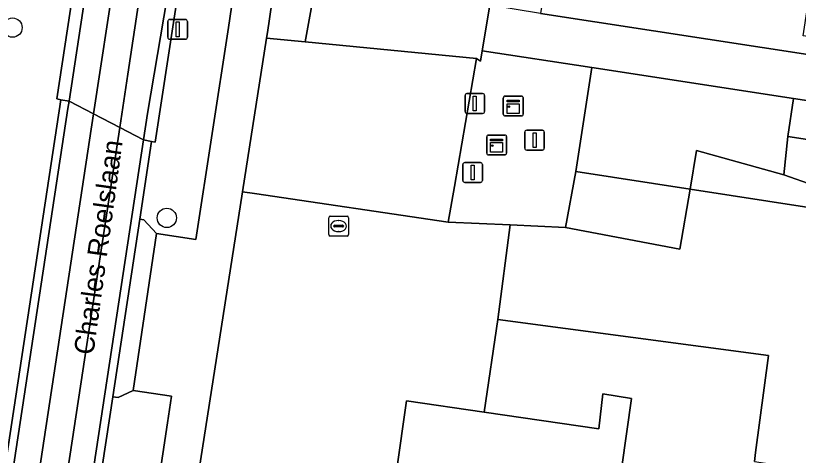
# Model space of a CAD drawing. Extents: x 161090 to 161692, y 379509 to 380907.
# Drawn here: x 161342.3 to 161381.89, y 380360.48 to 380382.7 of the extents above; entities that cross this region are included whole.
import ezdxf

# ---------------------------------------------------------------- set-up
doc = ezdxf.new("R2010")
doc.units = 0
for name, color, linetype in [('IMGEO_Berm_open', 7, 'Continuous'), ('IMGEO_Boom', 7, 'Continuous'), ('IMGEO_Groenvoorziening', 7, 'Continuous'), ('IMGEO_Hek', 7, 'Continuous'), ('IMGEO_Kast', 7, 'Continuous'), ('IMGEO_Kolk', 7, 'Continuous'), ('IMGEO_Lichtmast', 7, 'Continuous'), ('IMGEO_Openbare_ruimte_label', 7, 'Continuous'), ('IMGEO_Pand', 7, 'Continuous'), ('IMGEO_Rijbaan_lokaal_gesloten', 7, 'Continuous'), ('IMGEO_Rijbaan_lokaal_open', 7, 'Continuous'), ('IMGEO_Voetpad_gesloten', 7, 'Continuous'), ('IMGEO_Voetpad_open', 7, 'Continuous')]:
    doc.layers.add(name, color=color, linetype=linetype)

msp = doc.modelspace()

# ---------------------------------------------------------------- linework, layer by layer
at = {"layer": 'IMGEO_Berm_open'}
for points in [[(161355.725, 380448.967), (161357.571, 380461.128), (161356.996, 380461.235), (161355.421, 380450.894), (161355.14, 380449.051), (161354.011, 380441.643), (161344.389, 380378.487), (161344.59, 380378.452), (161345.007, 380378.379)], [(161359.36, 380442.076), (161359.664, 380444.186), (161360.3, 380448.307), (161362.175, 380460.46), (161361.586, 380460.548), (161359.751, 380448.386), (161350.135, 380384.631), (161348.977, 380377.751), (161348.775, 380376.428), (161349.181, 380376.34), (161349.368, 380376.3), (161352.303, 380395.563), (161352.6, 380397.59)], [(161344.951, 380378.008), (161345.007, 380378.379), (161344.59, 380378.452), (161324.892, 380248.973), (161324.162, 380244.173), (161321.656, 380227.7), (161322.076, 380227.626)], [(161334.619, 380280.903), (161334.854, 380282.447), (161335.341, 380285.645), (161335.901, 380289.318), (161337.021, 380296.658), (161337.547, 380300.102), (161339.301, 380311.601), (161339.84, 380315.127), (161341.641, 380326.929), (161347.212, 380363.435), (161348.583, 380372.419), (161349.181, 380376.34), (161348.775, 380376.428), (161335.506, 380289.381), (161325.446, 380223.42), (161325.852, 380223.354), (161325.866, 380223.448)]]:
    msp.add_lwpolyline(points, close=True, dxfattribs=at)
at = {"layer": 'IMGEO_Boom'}
for centre in [(161342.145, 380382.093), (161349.949, 380372.477)]:
    msp.add_circle(centre, 0.489, dxfattribs=at)
at = {"layer": 'IMGEO_Groenvoorziening'}
for points in [[(161348.425, 380442.457), (161348.083, 380442.507), (161347.809, 380440.721), (161343.094, 380410), (161341.258, 380398.041), (161340.185, 380394.742), (161339.9, 380392.897), (161338.488, 380392.532), (161338.415, 380392.044), (161337.94, 380388.87), (161317.884, 380254.93), (161315.312, 380255.309), (161314.369, 380249.618), (161321.492, 380248.501), (161324.892, 380248.973), (161344.59, 380378.452), (161344.389, 380378.487), (161354.011, 380441.643), (161348.796, 380442.403), (161319.973, 380254.612), (161319.602, 380254.669)], [(161359.874, 380397.513), (161357.564, 380396.909), (161356.103, 380388.816), (161355.909, 380387.739), (161355.043, 380381.85), (161354.998, 380381.564), (161356.953, 380381.374)], [(161353.938, 380388.06), (161354.108, 380389.079), (161354.875, 380393.67), (161355.424, 380396.33), (161352.303, 380395.563), (161349.368, 380376.3), (161349.181, 380376.34), (161348.583, 380372.419), (161348.788, 380372.383), (161349.424, 380371.695), (161351.411, 380371.391), (161353.061, 380382.104)], [(161384.783, 380376.062), (161381.353, 380376.586), (161381.163, 380374.657), (161382.693, 380374.109), (161384.386, 380373.456), (161384.274, 380372.724), (161463.887, 380360.513), (161466.132, 380360.169), (161466.151, 380360.297), (161470.678, 380359.631), (161470.78, 380360.312), (161470.639, 380361.064), (161470.9, 380361.114), (161471.145, 380362.753), (161471.162, 380362.866)], [(161349.991, 380362.127), (161350.192, 380363.472), (161348.24, 380363.761), (161347.497, 380363.399), (161347.212, 380363.435), (161341.641, 380326.929), (161344.627, 380326.528)]]:
    msp.add_lwpolyline(points, close=True, dxfattribs=at)
msp.add_lwpolyline([(161364.934, 380398.835), (161359.874, 380397.513), (161356.953, 380381.374), (161365.618, 380380.527), (161365.81, 380380.399), (161365.899, 380380.919), (161366.293, 380383.221), (161368.167, 380395.546), (161366.26, 380395.866), (161366.584, 380397.823)], dxfattribs=at)
at = {"layer": 'IMGEO_Hek'}
for points in [[(161365.618, 380380.527), (161364.502, 380374.068)], [(161370.631, 380374.817), (161371.438, 380380.074)], [(161370.107, 380371.989), (161370.631, 380374.817)], [(161384.274, 380372.724), (161370.631, 380374.817)], [(161364.502, 380374.068), (161364.182, 380372.262)], [(161364.182, 380372.262), (161354.392, 380373.71)], [(161364.182, 380372.262), (161367.309, 380372.118)], [(161367.309, 380372.118), (161366.698, 380367.337)], [(161367.309, 380372.118), (161370.107, 380371.989)], [(161366.002, 380362.661), (161366.698, 380367.337)], [(161366.698, 380367.337), (161380.378, 380365.515), (161379.726, 380360.615), (161379.666, 380360.168)]]:
    msp.add_lwpolyline(points, dxfattribs=at)
at = {"layer": 'IMGEO_Kast'}
for p, q in [((161366.969, 380377.708), (161366.969, 380378.549)), ((161366.969, 380378.549), (161366.969, 380377.708)), ((161367.044, 380378.633), (161367.885, 380378.633)), ((161367.885, 380378.633), (161367.044, 380378.633)), ((161367.969, 380378.558), (161367.969, 380377.717)), ((161367.969, 380377.717), (161367.969, 380378.558)), ((161367.894, 380377.633), (161367.053, 380377.633)), ((161367.053, 380377.633), (161367.894, 380377.633)), ((161366.133, 380375.741), (161366.133, 380376.582)), ((161366.133, 380376.582), (161366.133, 380375.741)), ((161366.208, 380376.666), (161367.049, 380376.666)), ((161367.049, 380376.666), (161366.208, 380376.666)), ((161367.133, 380376.591), (161367.133, 380375.75)), ((161367.133, 380375.75), (161367.133, 380376.591)), ((161367.058, 380375.666), (161366.217, 380375.666)), ((161366.217, 380375.666), (161367.058, 380375.666))]:
    msp.add_line(p, q, dxfattribs=at)
for points in [[(161367.164, 380378.423), (161367.764, 380378.423), (161367.764, 380378.338), (161367.164, 380378.338), (161367.164, 380378.423)], [(161367.164, 380378.248), (161367.764, 380378.248), (161367.764, 380377.759), (161367.164, 380377.759), (161367.164, 380378.248)], [(161366.328, 380376.456), (161366.928, 380376.456), (161366.928, 380376.371), (161366.328, 380376.371), (161366.328, 380376.456)], [(161366.328, 380376.281), (161366.928, 380376.281), (161366.928, 380375.792), (161366.328, 380375.792), (161366.328, 380376.281)]]:
    msp.add_lwpolyline(points, dxfattribs=at)
for centre in [(161367.248, 380378.097), (161366.412, 380376.13)]:
    msp.add_circle(centre, 0.0377, dxfattribs=at)
for centre, start, end in [((161367.047, 380378.555), 92.4484, 184.2845), ((161367.047, 380378.555), 92.4484, 184.2845), ((161367.891, 380378.555), 2.4484, 94.2845), ((161367.891, 380378.555), 2.4484, 94.2845), ((161367.047, 380377.711), 182.4484, 274.2845), ((161367.047, 380377.711), 182.4484, 274.2845), ((161367.891, 380377.711), 272.4484, 4.2845), ((161367.891, 380377.711), 272.4484, 4.2845), ((161366.211, 380376.588), 92.4484, 184.2845), ((161366.211, 380376.588), 92.4484, 184.2845), ((161367.055, 380376.588), 2.4484, 94.2845), ((161367.055, 380376.588), 2.4484, 94.2845), ((161366.211, 380375.744), 182.4484, 274.2845), ((161366.211, 380375.744), 182.4484, 274.2845), ((161367.055, 380375.744), 272.4484, 4.2845), ((161367.055, 380375.744), 272.4484, 4.2845)]:
    msp.add_arc(centre, 0.0779, start, end, dxfattribs=at)
at = {"layer": 'IMGEO_Kolk'}
for p, q in [((161358.139, 380371.636), (161358.139, 380372.488)), ((161358.214, 380372.562), (161359.066, 380372.562)), ((161359.14, 380372.488), (161359.14, 380371.636)), ((161358.441, 380372.105), (161358.839, 380372.105)), ((161358.627, 380372.342), (161358.652, 380372.342)), ((161358.398, 380372.056), (161358.398, 380372.068)), ((161358.836, 380372.019), (161358.438, 380372.019)), ((161358.65, 380371.782), (161358.625, 380371.782)), ((161358.882, 380372.068), (161358.882, 380372.056)), ((161359.066, 380371.562), (161358.214, 380371.562))]:
    msp.add_line(p, q, dxfattribs=at)
for points in [[(161358.139, 380371.636), (161358.139, 380372.488)], [(161358.214, 380372.562), (161359.066, 380372.562)], [(161359.14, 380372.488), (161359.14, 380371.636)], [(161359.066, 380371.562), (161358.214, 380371.562)]]:
    msp.add_lwpolyline(points, dxfattribs=at)
for centre, radius, start, end in [((161358.216, 380372.486), 0.0765, 91.552, 178.448), ((161358.216, 380372.486), 0.0765, 91.552, 178.448), ((161359.064, 380372.486), 0.0765, 1.552, 88.448), ((161359.064, 380372.486), 0.0765, 1.552, 88.448), ((161358.438, 380372.065), 0.0403, 85.8775, 175.7526), ((161358.843, 380372.067), 0.0386, 1.7309, 96.639), ((161358.435, 380372.055), 0.0366, 178.938, 274.7102), ((161358.839, 380372.062), 0.043, 264.8664, 352.4533), ((161358.216, 380371.638), 0.0765, 181.552, 268.448), ((161358.216, 380371.638), 0.0765, 181.552, 268.448), ((161359.064, 380371.638), 0.0765, 271.552, 358.448), ((161359.064, 380371.638), 0.0765, 271.552, 358.448)]:
    msp.add_arc(centre, radius, start, end, dxfattribs=at)
for centre, major_axis, ratio, start_param, end_param in [((161358.626, 380372.062), (-0.387, 0.002), 0.722429, 4.712389, 7.853982), ((161358.651, 380372.062), (-0.39, 0.002), 0.717154, 1.570796, 4.712389)]:
    msp.add_ellipse(centre, major_axis=major_axis, ratio=ratio, start_param=start_param, end_param=end_param, dxfattribs=at)
at = {"layer": 'IMGEO_Lichtmast'}
for p, q in [((161349.998, 380381.605), (161349.998, 380382.405)), ((161349.998, 380382.405), (161349.998, 380381.605)), ((161350.098, 380382.505), (161350.888, 380382.505)), ((161350.888, 380382.505), (161350.098, 380382.505)), ((161350.988, 380382.405), (161350.988, 380381.605)), ((161350.988, 380381.605), (161350.988, 380382.405)), ((161350.888, 380381.505), (161350.098, 380381.505)), ((161350.098, 380381.505), (161350.888, 380381.505)), ((161365.031, 380377.861), (161365.031, 380378.661)), ((161365.031, 380378.661), (161365.031, 380377.861)), ((161365.131, 380378.761), (161365.921, 380378.761)), ((161365.921, 380378.761), (161365.131, 380378.761)), ((161366.021, 380378.661), (161366.021, 380377.861)), ((161366.021, 380377.861), (161366.021, 380378.661)), ((161365.921, 380377.761), (161365.131, 380377.761)), ((161365.131, 380377.761), (161365.921, 380377.761)), ((161368.152, 380376.906), (161368.942, 380376.906)), ((161368.942, 380376.906), (161368.152, 380376.906)), ((161368.052, 380376.006), (161368.052, 380376.806)), ((161368.052, 380376.806), (161368.052, 380376.006)), ((161369.042, 380376.806), (161369.042, 380376.006)), ((161369.042, 380376.006), (161369.042, 380376.806)), ((161368.942, 380375.906), (161368.152, 380375.906)), ((161368.152, 380375.906), (161368.942, 380375.906)), ((161365.02, 380375.269), (161365.81, 380375.269)), ((161365.81, 380375.269), (161365.02, 380375.269)), ((161364.92, 380374.369), (161364.92, 380375.169)), ((161364.92, 380375.169), (161364.92, 380374.369)), ((161365.91, 380375.169), (161365.91, 380374.369)), ((161365.91, 380374.369), (161365.91, 380375.169)), ((161365.81, 380374.269), (161365.02, 380374.269)), ((161365.02, 380374.269), (161365.81, 380374.269))]:
    msp.add_line(p, q, dxfattribs=at)
for points in [[(161350.418, 380382.38), (161350.568, 380382.38), (161350.568, 380381.63), (161350.418, 380381.63), (161350.418, 380382.38)], [(161365.451, 380378.636), (161365.601, 380378.636), (161365.601, 380377.886), (161365.451, 380377.886), (161365.451, 380378.636)], [(161368.472, 380376.781), (161368.622, 380376.781), (161368.622, 380376.031), (161368.472, 380376.031), (161368.472, 380376.781)], [(161365.34, 380375.144), (161365.49, 380375.144), (161365.49, 380374.394), (161365.34, 380374.394), (161365.34, 380375.144)]]:
    msp.add_lwpolyline(points, dxfattribs=at)
for centre, start, end in [((161350.098, 380382.405), 90, 180), ((161350.098, 380382.405), 90, 180), ((161350.888, 380382.405), 0, 90), ((161350.888, 380382.405), 360, 90), ((161350.098, 380381.605), 180, 270), ((161350.098, 380381.605), 180, 270), ((161350.888, 380381.605), 270, 0), ((161350.888, 380381.605), 270, 0), ((161365.131, 380378.661), 90, 180), ((161365.131, 380378.661), 90, 180), ((161365.921, 380378.661), 0, 90), ((161365.921, 380378.661), 360, 90), ((161365.131, 380377.861), 180, 270), ((161365.131, 380377.861), 180, 270), ((161365.921, 380377.861), 270, 0), ((161365.921, 380377.861), 270, 0), ((161368.152, 380376.806), 90, 180), ((161368.152, 380376.806), 90, 180), ((161368.942, 380376.806), 0, 90), ((161368.942, 380376.806), 360, 90), ((161368.152, 380376.006), 180, 270), ((161368.152, 380376.006), 180, 270), ((161368.942, 380376.006), 270, 0), ((161368.942, 380376.006), 270, 0), ((161365.02, 380375.169), 90, 180), ((161365.02, 380375.169), 90, 180), ((161365.81, 380375.169), 0, 90), ((161365.81, 380375.169), 360, 90), ((161365.02, 380374.369), 180, 270), ((161365.02, 380374.369), 180, 270), ((161365.81, 380374.369), 270, 0), ((161365.81, 380374.369), 270, 0)]:
    msp.add_arc(centre, 0.1, start, end, dxfattribs=at)
at = {"layer": 'IMGEO_Pand'}
msp.add_lwpolyline([(161372.961, 380359.891), (161373.459, 380363.357), (161372.008, 380363.588), (161371.8, 380361.818), (161366.002, 380362.661), (161362.072, 380363.233), (161361.053, 380356.126)], dxfattribs=at)
at = {"layer": 'IMGEO_Rijbaan_lokaal_gesloten'}
for points in [[(161359.092, 380463.074), (161357.904, 380463.25), (161357.736, 380462.181), (161357.571, 380461.128), (161355.725, 380448.967), (161345.007, 380378.379), (161346.249, 380377.736), (161347.339, 380384.899), (161352.727, 380420.46), (161357.973, 380455.328)], [(161348.977, 380377.751), (161350.135, 380384.631), (161359.751, 380448.386), (161361.586, 380460.548), (161361.602, 380460.656), (161361.863, 380462.665), (161360.548, 380462.859), (161354.389, 380422.138), (161347.982, 380379.737), (161347.572, 380377.051), (161348.775, 380376.428)]]:
    msp.add_lwpolyline(points, close=True, dxfattribs=at)
for points in [[(161317.471, 380188.836), (161329.956, 380271.064), (161337.144, 380317.912), (161346.249, 380377.736), (161345.007, 380378.379), (161344.951, 380378.008), (161322.076, 380227.626)], [(161325.446, 380223.42), (161335.506, 380289.381), (161348.775, 380376.428), (161347.572, 380377.051), (161337.64, 380311.897), (161331.61, 380272.482), (161327.257, 380243.533)]]:
    msp.add_lwpolyline(points, dxfattribs=at)
at = {"layer": 'IMGEO_Rijbaan_lokaal_open'}
for points in [[(161360.548, 380462.859), (161361.17, 380466.972), (161359.681, 380467.147), (161359.092, 380463.074), (161357.973, 380455.328), (161352.727, 380420.46), (161347.339, 380384.899), (161346.249, 380377.736), (161347.572, 380377.051), (161347.982, 380379.737), (161354.389, 380422.138)], [(161347.572, 380377.051), (161346.249, 380377.736), (161337.144, 380317.912), (161329.956, 380271.064), (161317.471, 380188.836), (161318.978, 380188.612), (161322.079, 380209.661), (161327.257, 380243.533), (161331.61, 380272.482), (161337.64, 380311.897)]]:
    msp.add_lwpolyline(points, close=True, dxfattribs=at)
at = {"layer": 'IMGEO_Voetpad_gesloten'}
for points in [[(161371.438, 380380.074), (161381.648, 380378.516), (161468.018, 380365.334), (161469.294, 380373.89), (161477.35, 380372.681), (161481.559, 380372.049), (161482.201, 380376.134), (161469.916, 380377.934), (161470.53, 380381.972), (161468.256, 380382.316), (161466.073, 380367.985), (161458.115, 380369.198), (161453.409, 380369.922), (161425.969, 380374.048), (161399.728, 380378.077), (161368.855, 380382.814), (161366.293, 380383.221), (161365.899, 380380.919)], [(161381.163, 380374.657), (161376.746, 380375.877), (161376.415, 380373.93), (161384.274, 380372.724), (161384.386, 380373.456), (161382.693, 380374.109)], [(161366.698, 380367.337), (161367.309, 380372.118), (161364.182, 380372.262), (161354.392, 380373.71), (161353.781, 380373.8), (161351.226, 380357.502), (161351.919, 380357.419), (161354.512, 380357.063), (161361.053, 380356.126), (161362.072, 380363.233), (161366.002, 380362.661)]]:
    msp.add_lwpolyline(points, close=True, dxfattribs=at)
msp.add_lwpolyline([(161460.946, 380351.094), (161448.797, 380352.894), (161449.083, 380354.725), (161436.203, 380356.676), (161429.707, 380357.659), (161415.274, 380359.844), (161395.006, 380363.008), (161386.168, 380368.414), (161383.79, 380369.549), (161384.274, 380372.724), (161376.415, 380373.93), (161375.899, 380370.898), (161370.107, 380371.989), (161367.309, 380372.118), (161366.698, 380367.337), (161380.378, 380365.515), (161379.726, 380360.615), (161379.666, 380360.168), (161456.714, 380348.489), (161452.235, 380318.578)], dxfattribs=at)
at = {"layer": 'IMGEO_Voetpad_open'}
for points in [[(161475.669, 380430.786), (161442.92, 380435.825), (161442.702, 380434.464), (161426.695, 380436.945), (161426.845, 380438.036), (161441.518, 380435.817), (161441.558, 380436.032), (161425.407, 380438.468), (161425.207, 380436.998), (161404.093, 380440.226), (161404.319, 380441.69), (161378.471, 380445.674), (161377.808, 380441.418), (161375.516, 380426.06), (161371.977, 380402.925), (161373.421, 380402.686), (161372.216, 380394.847), (161370.769, 380395.064), (161368.855, 380382.814), (161399.728, 380378.077), (161399.864, 380378.968), (161382.131, 380381.674), (161391.017, 380439.754), (161473.226, 380427.168)], [(161379.666, 380360.168), (161379.726, 380360.615), (161380.378, 380365.515), (161366.698, 380367.337), (161366.002, 380362.661), (161371.8, 380361.818), (161372.008, 380363.588), (161373.459, 380363.357), (161372.961, 380359.891)]]:
    msp.add_lwpolyline(points, dxfattribs=at)
for points in [[(161353.781, 380373.8), (161354.998, 380381.564), (161355.043, 380381.85), (161355.909, 380387.739), (161356.103, 380388.816), (161354.108, 380389.079), (161353.938, 380388.06), (161353.061, 380382.104), (161351.411, 380371.391), (161349.424, 380371.695), (161348.24, 380363.761), (161350.192, 380363.472), (161349.991, 380362.127), (161344.627, 380326.528), (161346.334, 380326.298), (161351.226, 380357.502)], [(161356.953, 380381.374), (161354.998, 380381.564), (161353.781, 380373.8), (161354.392, 380373.71), (161364.182, 380372.262), (161364.502, 380374.068), (161365.618, 380380.527)], [(161370.107, 380371.989), (161370.631, 380374.817), (161371.438, 380380.074), (161365.899, 380380.919), (161365.81, 380380.399), (161365.618, 380380.527), (161364.502, 380374.068), (161364.182, 380372.262), (161367.309, 380372.118)], [(161381.648, 380378.516), (161371.438, 380380.074), (161370.631, 380374.817), (161376.415, 380373.93), (161376.746, 380375.877), (161381.163, 380374.657), (161381.353, 380376.586)], [(161381.648, 380378.516), (161381.353, 380376.586), (161384.783, 380376.062), (161471.162, 380362.866), (161476.123, 380362.108), (161476.547, 380362.043), (161484.786, 380360.785), (161485.084, 380362.709), (161476.023, 380364.103), (161468.018, 380365.334)], [(161376.415, 380373.93), (161370.631, 380374.817), (161370.107, 380371.989), (161375.899, 380370.898)], [(161349.424, 380371.695), (161348.788, 380372.383), (161348.583, 380372.419), (161347.212, 380363.435), (161347.497, 380363.399), (161348.24, 380363.761)]]:
    msp.add_lwpolyline(points, close=True, dxfattribs=at)

# ---------------------------------------------------------------- texts
at = {"layer": 'IMGEO_Openbare_ruimte_label'}
msp.add_text('Charles Roelslaan', height=1, rotation=82.1858, dxfattribs=at).set_placement((161346.232, 380365.517))

doc.saveas('drawing.dxf')
